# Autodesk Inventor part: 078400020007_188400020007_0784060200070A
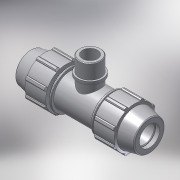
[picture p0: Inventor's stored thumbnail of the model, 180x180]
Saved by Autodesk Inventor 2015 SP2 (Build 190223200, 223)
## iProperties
Created: 2017-02
Part Number: 078400020007_188400020007_0784060200070A
Material: PVC-Piping
Description: PLASSON TEE WITH THREADED MALE OFFTAKE 20-3/4"-20
Document SubType Name: Modeling
Designer: KIM
Mass: 92.6774 g
Surface Area: 199.44 cm^2
Volume: 66.1981 cm^3
Density: 1.4 g/cm^3
Appearance: Smooth - White
Author: Кирилл
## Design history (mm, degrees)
derived "07840.ipt"
feature "Solid1::07840.ipt"
feature "Solid2::07840.ipt"
tag "TaggingFeature1"
body "Solid1"
body "Solid2"
other parameters: "d4" = 6, "d5" = 17.28, "d7" = 48, "d11" = 2.4, "d13" = 120 deg, "d15" = 12 deg, "d16" = 41.76, "d18" = 1, "d19" = 35 deg, "d20" = 17.5 deg, "d21" = 44.64, "d23" = 0, "d25" = 360 deg, "d27" = 0.96, "d33" = 0.4, "d42" = 25.92, "d43" = 1.44, "d46" = 0.6, "d68" = 2.4, "d72" = 46, "d73" = 26.441, "d74" = 18, "d75" = 30.40715, "d76" = 18.5087, "d77" = 21.6, "d80" = 0.79323, "d91" = 36, "d93" = 56, "d95" = 18, "d99" = 144, "d101" = 0, "d103" = 0, "d105" = 0, "E_" = 48, "A_" = 46, "l_" = 56, "l_2" = 18, "H_" = 144, "R_" = 26.441
